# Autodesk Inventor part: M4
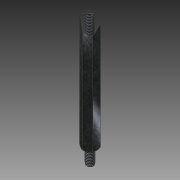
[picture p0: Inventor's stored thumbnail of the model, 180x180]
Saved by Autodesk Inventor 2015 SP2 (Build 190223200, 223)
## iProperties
Created: 2012-08
Part Number: M4
Material: Stahl
Document SubType Name: Modeling
Designer: rYan
Density: 7.85 g/cm^3
Mass: 1.74537 g
Surface Area: 3.04272 cm^2
Volume: 0.22234 cm^3
Appearance: Platte
Author: rYan
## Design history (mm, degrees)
derived "Abstandsbolzen Typ B.ipt"
feature "Volumenkörper1::Abstandsbolzen Typ B.ipt"
tag "Bezeichnung1"
node "Volumenkörper1"
other parameters: "SW" = 7, "d2" = 0, "d9" = 118 deg, "GA_" = 4, "A_" = 8, "d13" = 0, "d17" = 0.25, "d20" = 45 deg
